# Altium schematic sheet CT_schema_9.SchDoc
size 308 x 210 mm
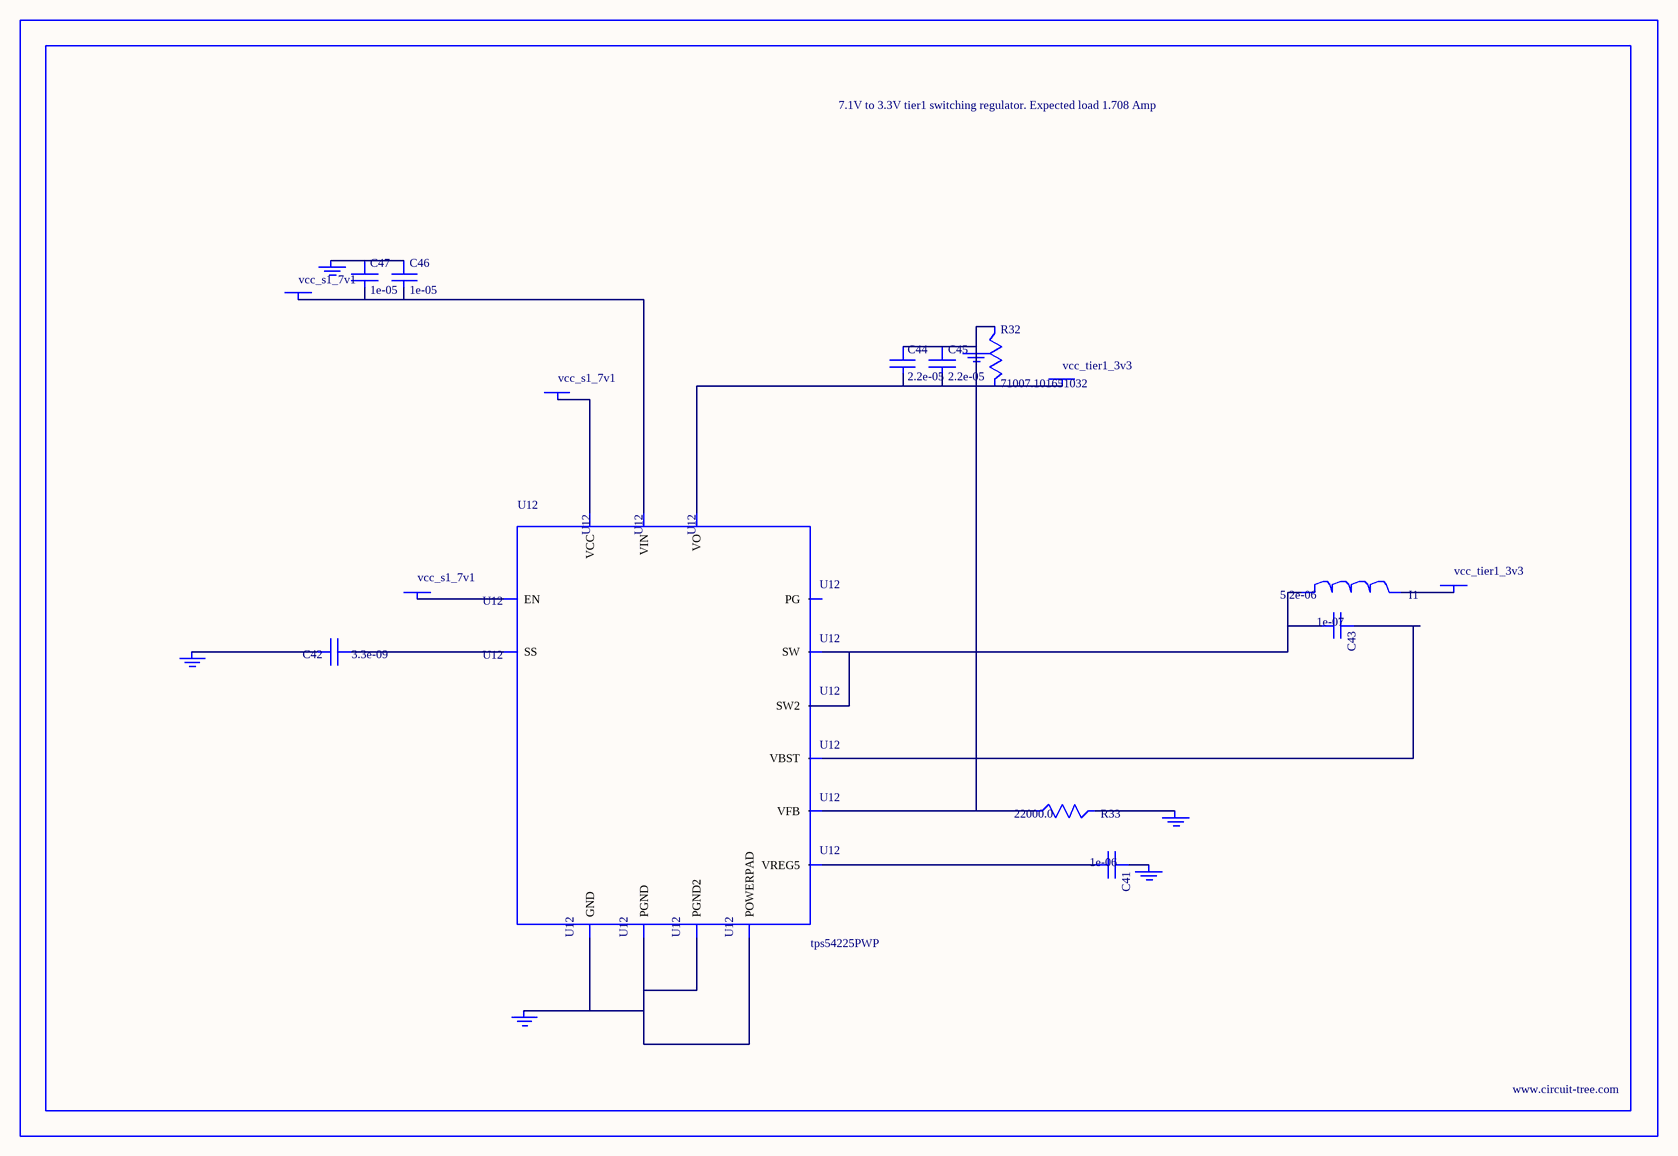
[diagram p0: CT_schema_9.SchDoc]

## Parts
BORDER8  (no value)
C41  1e-06  [C0603]
C42  3.3e-09  [C0402]
C43  1e-07  [C0402]
C44  2.2e-05  [C1210]
C45  2.2e-05  [C1210]
C46  1e-05  [C1206]
C47  1e-05  [C1206]
GND_INSTANCE_8_0  (no value)
GND_INSTANCE_8_1  (no value)
GND_INSTANCE_8_2  (no value)
GND_INSTANCE_8_3  (no value)
GND_INSTANCE_8_4  (no value)
GND_INSTANCE_8_5  (no value)
I1  5.2e-06  [DR1040]
POWER_INSTANCE_8_0  vcc_tier1_3v3
POWER_INSTANCE_8_1  vcc_s1_7v1
POWER_INSTANCE_8_2  vcc_tier1_3v3
POWER_INSTANCE_8_3  vcc_s1_7v1
POWER_INSTANCE_8_4  vcc_s1_7v1
R32  71007.101651032  [R0603]
R33  22000.0  [R0603]
U12  tps54225PWP  [HTSSOP14]

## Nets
NetC41_1: C41.1 GND_INSTANCE_8_2.0(GND)
NetC41_2: C41.2 U12.3(VREG5)
NetC42_1: C42.1 U12.4(SS)
NetC42_2: C42.2 GND_INSTANCE_8_3.0(GND)
NetC43_1: C43.1 U12.12(VBST)
NetC43_2: C43.2 I1.1 U12.10(SW) U12.11(SW2)
NetC44_1: C44.1 C45.1 GND_INSTANCE_8_0.0(GND) R32.1 R33.1 U12.2(VFB)
NetC44_2: C44.2 C45.2 POWER_INSTANCE_8_0.0(PWR) R32.2 U12.1(VO)
NetC46_1: C46.1 C47.1 GND_INSTANCE_8_5.0(GND)
NetC46_2: C46.2 C47.2 POWER_INSTANCE_8_3.0(PWR) U12.13(VIN)
NetGND_INSTANCE_8_1_0: GND_INSTANCE_8_1.0(GND) R33.2
NetGND_INSTANCE_8_4_0: GND_INSTANCE_8_4.0(GND) U12.5(GND) U12.8(PGND) U12.9(PGND2) U12.15(POWERPAD)
NetI1_2: I1.2 POWER_INSTANCE_8_2.0(PWR)
NetPOWER_INSTANCE_8_1_0: POWER_INSTANCE_8_1.0(PWR) U12.7(EN)
NetPOWER_INSTANCE_8_4_0: POWER_INSTANCE_8_4.0(PWR) U12.14(VCC)

Not connected (* = marked no-connect by the designer): U12 6(PG)

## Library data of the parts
BORDER8 = BORDER_PAGE8
C41 = C0603C105K3RACTU
C42 = C0402C332K3RAC
C43 = C0402C104K3RACTU
C44 C45 = GRM32ER61E226ME15L
C46 C47 = C1206C106K3RACTU
GND_INSTANCE_8_0-GND_INSTANCE_8_5 = GND
I1 = DR1040-5R2-R
POWER_INSTANCE_8_0-POWER_INSTANCE_8_4 = PWR
R32 = R32
R33 = RC0603JR-0722KL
